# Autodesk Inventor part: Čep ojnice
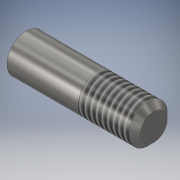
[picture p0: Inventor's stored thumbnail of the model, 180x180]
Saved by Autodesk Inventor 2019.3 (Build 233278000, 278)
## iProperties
Created: 2019-02
Part Number: Čep ojnice
Material: Ocel, legovaná
Document SubType Name: Modeling
Designer: B-hon
Density: 7.73 g/cm^3
Appearance: Pololeštěná
Author: B-hon
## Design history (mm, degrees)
sketch "Náčrt1"
  geometry: L1 (0, 0)-(40, 0) reference; L2 (0, 0)-(0, 6); L3 (0, 6)-(40, 6); L4 (40, 6)-(40, 0)
  constraints: 9 end point, 2 horizontal, 2 perpendicular, 1 vertical
  dimensions: "d0" = 12 diameter of L3 L1; "d1" = 40 distance of L2.end L3.end
revolve "Rotace1" sketch "Náčrt1" stored, may be unused: angle "d2" = 90 deg
chamfer "Zkosení1" distance "d3" = 1.8; stored, may be unused: second distance "d4" = 2, angle "d5" = 45 deg
feature "Závit1" dims "d6" = 16, "d7" = 0
node "Těleso1"
